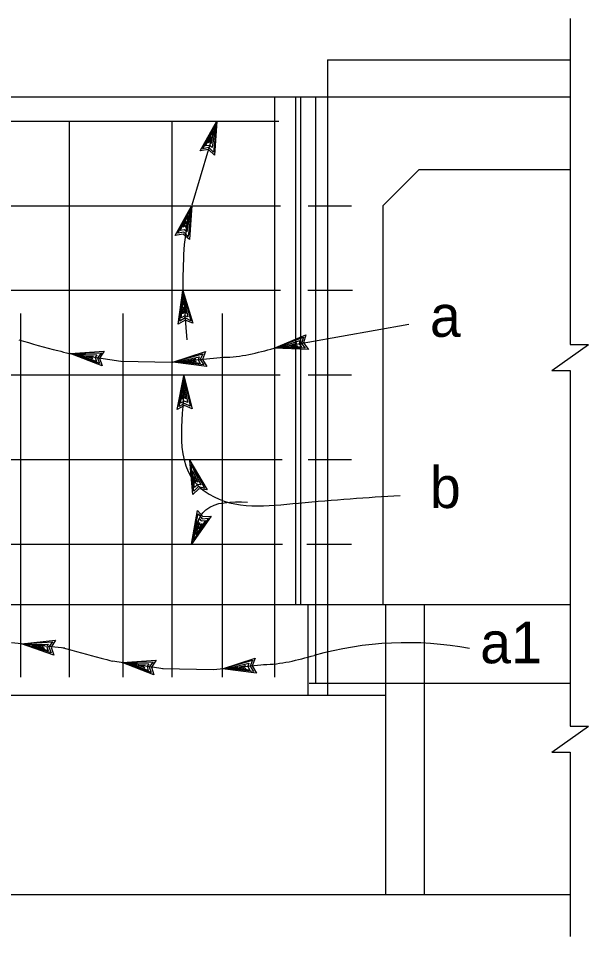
# Model space of a CAD drawing. Extents: x -0.08 to 2.83, y -0.03 to 1.92.
# Drawn here: x 0.4631 to 0.642, y 0.7605 to 1.0486 of the extents above; entities that cross this region are included whole.
import ezdxf

# ---------------------------------------------------------------- set-up
doc = ezdxf.new("R2010")
doc.units = 0
for name, color, linetype in [('50', 7, 'Continuous'), ('51', 7, 'Continuous'), ('55', 7, 'Continuous'), ('57', 7, 'Continuous')]:
    doc.layers.add(name, color=color, linetype=linetype)

msp = doc.modelspace()

# ---------------------------------------------------------------- linework, layer by layer
at = {"layer": '50'}
for p, q in [((0.56001, 1.03566), (0.56001, 1.024)), ((0.56001, 1.03566), (0.63617, 1.03566)), ((0.30166, 1.024), (0.63617, 1.024)), ((0.54996, 1.02381), (0.54996, 0.86462)), ((0.55155, 1.02395), (0.55155, 0.86476)), ((0.56001, 1.024), (0.56001, 0.8363)), ((0.57742, 0.98987), (0.58879, 1.00125)), ((0.58879, 1.00125), (0.63617, 1.00125)), ((0.57742, 0.98987), (0.57742, 0.86474)), ((0.26143, 0.86474), (0.63616, 0.86474)), ((0.55401, 0.8363), (0.55401, 0.86474)), ((0.57829, 0.86474), (0.57829, 0.77373)), ((0.59034, 0.86474), (0.59034, 0.77373)), ((0.55432, 0.84009), (0.63616, 0.84009)), ((0.31372, 0.8363), (0.57829, 0.8363)), ((0.31372, 0.77373), (0.63617, 0.77373))]:
    msp.add_line(p, q, dxfattribs=at)
at = {"layer": '51'}
for p, q in [((0.5434, 1.024), (0.5434, 0.84199)), ((0.55628, 1.024), (0.55628, 0.84009)), ((0.30816, 1.01641), (0.5448, 1.01641)), ((0.47904, 1.01641), (0.47904, 0.84199)), ((0.51122, 1.01641), (0.51122, 0.84199)), ((0.30816, 0.98987), (0.54532, 0.98987)), ((0.55402, 0.98987), (0.56754, 0.98987)), ((0.30816, 0.96333), (0.54532, 0.96333)), ((0.5539, 0.96333), (0.56792, 0.96333)), ((0.46374, 0.956), (0.46374, 0.84199)), ((0.49587, 0.956), (0.49587, 0.84199)), ((0.52703, 0.956), (0.52703, 0.84199)), ((0.30816, 0.93678), (0.54518, 0.93678)), ((0.55402, 0.93678), (0.56754, 0.93678)), ((0.30816, 0.91024), (0.5458, 0.91024)), ((0.55402, 0.91024), (0.56754, 0.91024)), ((0.30816, 0.8837), (0.54594, 0.8837)), ((0.5536, 0.8837), (0.56754, 0.8837))]:
    msp.add_line(p, q, dxfattribs=at)
at = {"layer": '55'}
for p, q in [((0.63617, 1.04865), (0.63616, 0.94628)), ((0.52532, 1.01641), (0.51749, 0.99005)), ((0.52009, 1.00704), (0.52532, 1.01641)), ((0.52094, 1.00774), (0.52494, 1.0151)), ((0.52494, 1.0151), (0.52382, 1.00816)), ((0.52532, 1.01641), (0.52425, 1.00668)), ((0.52532, 1.01641), (0.5246, 1.00571)), ((0.52174, 1.00862), (0.52423, 1.01326)), ((0.52267, 1.0096), (0.52369, 1.01144)), ((0.52369, 1.01144), (0.5234, 1.01049)), ((0.52423, 1.01326), (0.52354, 1.00935)), ((0.52306, 1.00878), (0.52174, 1.00862)), ((0.5234, 1.01018), (0.52267, 1.0096)), ((0.52382, 1.00816), (0.52306, 1.00878)), ((0.52354, 1.00935), (0.5234, 1.01018)), ((0.52267, 1.00747), (0.52009, 1.00704)), ((0.52286, 1.00813), (0.52094, 1.00774)), ((0.5246, 1.00571), (0.52267, 1.00747)), ((0.52425, 1.00668), (0.52286, 1.00813)), ((0.51222, 0.98055), (0.51745, 0.98991)), ((0.51306, 0.98126), (0.51706, 0.9886)), ((0.51706, 0.9886), (0.51595, 0.98166)), ((0.51745, 0.98991), (0.51638, 0.98019)), ((0.51745, 0.98991), (0.51673, 0.97922)), ((0.51387, 0.98212), (0.51636, 0.98676)), ((0.51636, 0.98676), (0.51567, 0.98285)), ((0.5148, 0.9831), (0.51582, 0.98494)), ((0.51553, 0.98369), (0.5148, 0.9831)), ((0.51567, 0.98285), (0.51553, 0.98369)), ((0.51582, 0.98494), (0.51554, 0.984)), ((0.5148, 0.98097), (0.51222, 0.98055)), ((0.51499, 0.98162), (0.51306, 0.98126)), ((0.51518, 0.98228), (0.51387, 0.98212)), ((0.51673, 0.97922), (0.5148, 0.98097)), ((0.51638, 0.98019), (0.51499, 0.98162)), ((0.51595, 0.98166), (0.51518, 0.98228)), ((0.51315, 0.95266), (0.51469, 0.96327)), ((0.51469, 0.96327), (0.51589, 0.94777)), ((0.51469, 0.96327), (0.51784, 0.95302)), ((0.51469, 0.96327), (0.51717, 0.9538)), ((0.51369, 0.95361), (0.51479, 0.96191)), ((0.51414, 0.95471), (0.51479, 0.95993)), ((0.51479, 0.96191), (0.51624, 0.95503)), ((0.51479, 0.95993), (0.51556, 0.95604)), ((0.51464, 0.95596), (0.51494, 0.95804)), ((0.51511, 0.95676), (0.51464, 0.95596)), ((0.51494, 0.95804), (0.51501, 0.95706)), ((0.51556, 0.95604), (0.51511, 0.95676)), ((0.51541, 0.95397), (0.51315, 0.95266)), ((0.51536, 0.95465), (0.51369, 0.95361)), ((0.51531, 0.95533), (0.51414, 0.95471)), ((0.51624, 0.95503), (0.51531, 0.95533)), ((0.51717, 0.9538), (0.51536, 0.95465)), ((0.51784, 0.95302), (0.51541, 0.95397)), ((0.54335, 0.94517), (0.5856, 0.95272)), ((0.54335, 0.94517), (0.55324, 0.94933)), ((0.54335, 0.94517), (0.55252, 0.94859)), ((0.55252, 0.94859), (0.55186, 0.94669)), ((0.55324, 0.94933), (0.55253, 0.94681)), ((0.55407, 0.94471), (0.54335, 0.94517)), ((0.54469, 0.94542), (0.5514, 0.94754)), ((0.55307, 0.94513), (0.54469, 0.94542)), ((0.54666, 0.94561), (0.55046, 0.94675)), ((0.55192, 0.94547), (0.54666, 0.94561)), ((0.54852, 0.94595), (0.5495, 0.94611)), ((0.55062, 0.94585), (0.54852, 0.94595)), ((0.55046, 0.94675), (0.54979, 0.94625)), ((0.54979, 0.94625), (0.55062, 0.94585)), ((0.5514, 0.94754), (0.55119, 0.94657)), ((0.55119, 0.94657), (0.55192, 0.94547)), ((0.55186, 0.94669), (0.55307, 0.94513)), ((0.55253, 0.94681), (0.55407, 0.94471)), ((0.63038, 0.93817), (0.64196, 0.94628)), ((0.63616, 0.94628), (0.64196, 0.94628)), ((0.47933, 0.94347), (0.49002, 0.94424)), ((0.47933, 0.94347), (0.4891, 0.94376)), ((0.47933, 0.94347), (0.49525, 0.94108)), ((0.48933, 0.93959), (0.47933, 0.94347)), ((0.48851, 0.94032), (0.48066, 0.94326)), ((0.48066, 0.94326), (0.48771, 0.94313)), ((0.48754, 0.941), (0.4826, 0.94282)), ((0.4826, 0.94282), (0.48656, 0.94268)), ((0.48643, 0.94178), (0.48447, 0.94254)), ((0.48447, 0.94254), (0.48545, 0.94239)), ((0.48656, 0.94268), (0.48576, 0.94242)), ((0.48576, 0.94242), (0.48643, 0.94178)), ((0.48771, 0.94313), (0.48719, 0.94229)), ((0.48719, 0.94229), (0.48754, 0.941)), ((0.4891, 0.94376), (0.48787, 0.94218)), ((0.48787, 0.94218), (0.48851, 0.94032)), ((0.49002, 0.94424), (0.48854, 0.94208)), ((0.51154, 0.94076), (0.52173, 0.94412)), ((0.51154, 0.94076), (0.52095, 0.94344)), ((0.51154, 0.94076), (0.52738, 0.94232)), ((0.5129, 0.9409), (0.51976, 0.94248)), ((0.51976, 0.94248), (0.51947, 0.94154)), ((0.52095, 0.94344), (0.52014, 0.94161)), ((0.52173, 0.94412), (0.52082, 0.94167)), ((0.48854, 0.94208), (0.48933, 0.93959)), ((0.49527, 0.94108), (0.51125, 0.94076)), ((0.52219, 0.93945), (0.51154, 0.94076)), ((0.52121, 0.93996), (0.5129, 0.9409)), ((0.51488, 0.94094), (0.51876, 0.94178)), ((0.52011, 0.94039), (0.51488, 0.94094)), ((0.51677, 0.94112), (0.51774, 0.94122)), ((0.51885, 0.94087), (0.51677, 0.94112)), ((0.51876, 0.94178), (0.51804, 0.94133)), ((0.51804, 0.94133), (0.51885, 0.94087)), ((0.51947, 0.94154), (0.52011, 0.94039)), ((0.52014, 0.94161), (0.52121, 0.93996)), ((0.52082, 0.94167), (0.52219, 0.93945)), ((0.5129, 0.92596), (0.51493, 0.9365)), ((0.51493, 0.9365), (0.51761, 0.92611)), ((0.51493, 0.9365), (0.51696, 0.92693)), ((0.63038, 0.93817), (0.63617, 0.93817)), ((0.63617, 0.93817), (0.63616, 0.82658)), ((0.51348, 0.92689), (0.51496, 0.93513)), ((0.51496, 0.93513), (0.51609, 0.92818)), ((0.51397, 0.92797), (0.51487, 0.93316)), ((0.51455, 0.9292), (0.51494, 0.93127)), ((0.51487, 0.93316), (0.51546, 0.92923)), ((0.51494, 0.93127), (0.51496, 0.93028)), ((0.51519, 0.92785), (0.51348, 0.92689)), ((0.51517, 0.92853), (0.51397, 0.92797)), ((0.51505, 0.92998), (0.51455, 0.9292)), ((0.51546, 0.92923), (0.51505, 0.92998)), ((0.51609, 0.92818), (0.51517, 0.92853)), ((0.51696, 0.92693), (0.51519, 0.92785)), ((0.51521, 0.92716), (0.5129, 0.92596)), ((0.51761, 0.92611), (0.51521, 0.92716)), ((0.51689, 0.90996), (0.52228, 0.90068)), ((0.51778, 0.89927), (0.51689, 0.90996)), ((0.51689, 0.90996), (0.52144, 0.9013)), ((0.51809, 0.90031), (0.5173, 0.90865)), ((0.5173, 0.90865), (0.52026, 0.90226)), ((0.51828, 0.90148), (0.51774, 0.90673)), ((0.51774, 0.90673), (0.51936, 0.9031)), ((0.5185, 0.90283), (0.51831, 0.90492)), ((0.51831, 0.90492), (0.51861, 0.90398)), ((0.51928, 0.90235), (0.51828, 0.90148)), ((0.51877, 0.90371), (0.5185, 0.90283)), ((0.51936, 0.9031), (0.51877, 0.90371)), ((0.52026, 0.90226), (0.51928, 0.90235)), ((0.51969, 0.90105), (0.51778, 0.89927)), ((0.51948, 0.90171), (0.51809, 0.90031)), ((0.52144, 0.9013), (0.51948, 0.90171)), ((0.52228, 0.90068), (0.51969, 0.90105)), ((0.51739, 0.8837), (0.51924, 0.89426)), ((0.51739, 0.8837), (0.51947, 0.89325)), ((0.51924, 0.89426), (0.52097, 0.89231)), ((0.51947, 0.89325), (0.52071, 0.89168)), ((0.52358, 0.89245), (0.51739, 0.8837)), ((0.52267, 0.89185), (0.51791, 0.88496)), ((0.51791, 0.88496), (0.51975, 0.89175)), ((0.52176, 0.89107), (0.51881, 0.88672)), ((0.51881, 0.88672), (0.5199, 0.89053)), ((0.51975, 0.89175), (0.52044, 0.89105)), ((0.5199, 0.89053), (0.51996, 0.88969)), ((0.52044, 0.89105), (0.52176, 0.89107)), ((0.52071, 0.89168), (0.52267, 0.89185)), ((0.52097, 0.89231), (0.52358, 0.89245)), ((0.52074, 0.89018), (0.51954, 0.88847)), ((0.51954, 0.88847), (0.51991, 0.88938)), ((0.51996, 0.88969), (0.52074, 0.89018)), ((0.46087, 0.85284), (0.47761, 0.85112)), ((0.46407, 0.85236), (0.47473, 0.85356)), ((0.46407, 0.85236), (0.47382, 0.85305)), ((0.47382, 0.85305), (0.47267, 0.85142)), ((0.47473, 0.85356), (0.47334, 0.85134)), ((0.47421, 0.84889), (0.46407, 0.85236)), ((0.46542, 0.85221), (0.47246, 0.85235)), ((0.47338, 0.84959), (0.46542, 0.85221)), ((0.46736, 0.85185), (0.47134, 0.85187)), ((0.47238, 0.85024), (0.46736, 0.85185)), ((0.47124, 0.85097), (0.46926, 0.85164)), ((0.46926, 0.85164), (0.47023, 0.85153)), ((0.47134, 0.85187), (0.47054, 0.85158)), ((0.47054, 0.85158), (0.47124, 0.85097)), ((0.47246, 0.85235), (0.47198, 0.8515)), ((0.47198, 0.8515), (0.47238, 0.85024)), ((0.47267, 0.85142), (0.47338, 0.84959)), ((0.47334, 0.85134), (0.47421, 0.84889)), ((0.49255, 0.84703), (0.50848, 0.84464)), ((0.4956, 0.84652), (0.5063, 0.84729)), ((0.5063, 0.84729), (0.50482, 0.84513)), ((0.52715, 0.84457), (0.53734, 0.84794)), ((0.52715, 0.84457), (0.53656, 0.84726)), ((0.53656, 0.84726), (0.53575, 0.84543)), ((0.53734, 0.84794), (0.53643, 0.84549)), ((0.4956, 0.84652), (0.50538, 0.84681)), ((0.5056, 0.84264), (0.4956, 0.84652)), ((0.50478, 0.84338), (0.49694, 0.84631)), ((0.49694, 0.84631), (0.50398, 0.84618)), ((0.50382, 0.84405), (0.49887, 0.84587)), ((0.49887, 0.84587), (0.50284, 0.84573)), ((0.5027, 0.84483), (0.50074, 0.84559)), ((0.50074, 0.84559), (0.50172, 0.84544)), ((0.50284, 0.84573), (0.50204, 0.84547)), ((0.50204, 0.84547), (0.5027, 0.84483)), ((0.50398, 0.84618), (0.50347, 0.84534)), ((0.50347, 0.84534), (0.50382, 0.84405)), ((0.50538, 0.84681), (0.50414, 0.84524)), ((0.50414, 0.84524), (0.50478, 0.84338)), ((0.50482, 0.84513), (0.5056, 0.84264)), ((0.50827, 0.84465), (0.52426, 0.84433)), ((0.5243, 0.84439), (0.54014, 0.84595)), ((0.5378, 0.84326), (0.52715, 0.84457)), ((0.52851, 0.84471), (0.53537, 0.8463)), ((0.53683, 0.84378), (0.52851, 0.84471)), ((0.53049, 0.84476), (0.53437, 0.84559)), ((0.53572, 0.8442), (0.53049, 0.84476)), ((0.53238, 0.84493), (0.53335, 0.84504)), ((0.53446, 0.84469), (0.53238, 0.84493)), ((0.53437, 0.84559), (0.53365, 0.84514)), ((0.53365, 0.84514), (0.53446, 0.84469)), ((0.53537, 0.8463), (0.53508, 0.84535)), ((0.53508, 0.84535), (0.53572, 0.8442)), ((0.53575, 0.84543), (0.53683, 0.84378)), ((0.53643, 0.84549), (0.5378, 0.84326)), ((0.63038, 0.81847), (0.64196, 0.82658)), ((0.63616, 0.82658), (0.64196, 0.82658)), ((0.63038, 0.81847), (0.63617, 0.81847)), ((0.63617, 0.81847), (0.63617, 0.76055))]:
    msp.add_line(p, q, dxfattribs=at)
msp.add_arc((0.58501, 0.74446), 0.1083, 79.5659, 105.599, dxfattribs=at)
for points in [[(0.51745, 0.98991), (0.51701, 0.98842), (0.51467, 0.96342)], [(0.46318, 0.94778), (0.47548, 0.94441), (0.47904, 0.94353)], [(0.5274, 0.94232), (0.52743, 0.94232), (0.5433, 0.94517)], [(0.51493, 0.9365), (0.51496, 0.9354), (0.51842, 0.90316), (0.52292, 0.89934), (0.55098, 0.89657), (0.58284, 0.899)], [(0.51739, 0.8837), (0.52188, 0.89449), (0.535, 0.89691)], [(0.47674, 0.85127), (0.48904, 0.8479), (0.49261, 0.84701)], [(0.53998, 0.84592), (0.54001, 0.84592), (0.55589, 0.84877)]]:
    msp.add_spline(points, degree=3, dxfattribs=at)

# ---------------------------------------------------------------- texts
at = {"layer": '57'}
for s, height, p in [('a', 0.01302, (0.59218, 0.94874)), ('b', 0.01302, (0.59218, 0.89502)), ('a1', 0.013021, (0.60794, 0.84631))]:
    msp.add_text(s, height=height, dxfattribs=at).set_placement(p)

doc.saveas('drawing.dxf')
